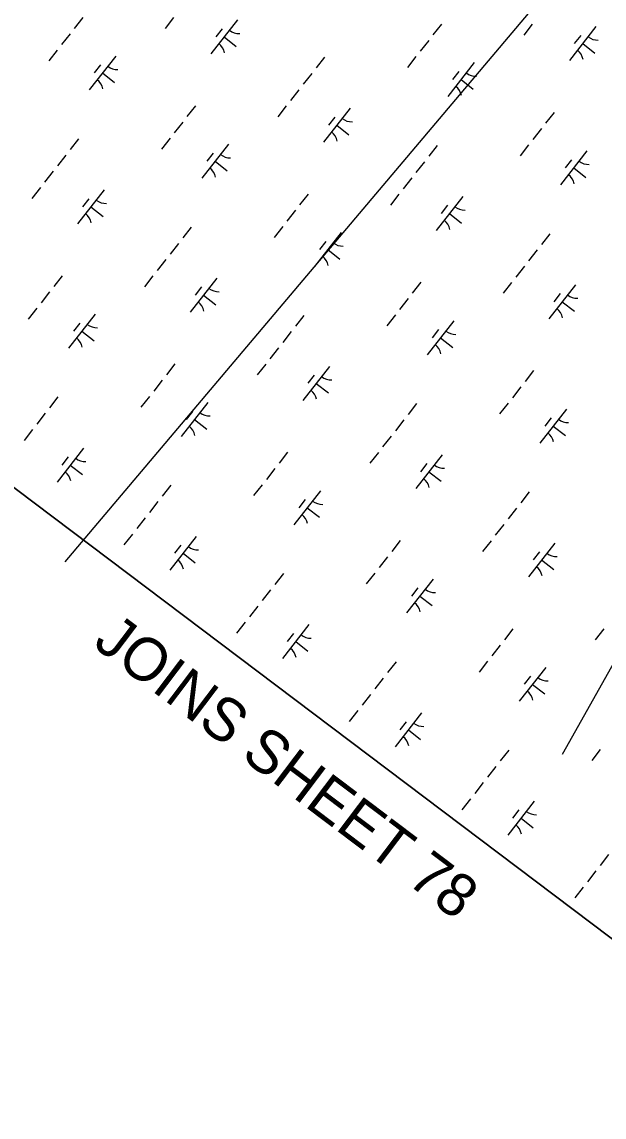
# Model space of a CAD drawing. Extents: x 3896831 to 3918110, y 171006 to 193349.
# Drawn here: x 3902228 to 3902905, y 175445 to 176718 of the extents above; entities that cross this region are included whole.
import ezdxf

# ---------------------------------------------------------------- set-up
doc = ezdxf.new("R2010")
doc.units = 0
for name, color, linetype in [('V-ANNO-TEXT', 7, 'Continuous'), ('V-GRID-FRAM', 7, 'Continuous'), ('V-UTIL-LINE', 7, 'Continuous'), ('V-WETL-SWMP', 7, 'Continuous')]:
    doc.layers.add(name, color=color, linetype=linetype)

msp = doc.modelspace()

# ---------------------------------------------------------------- linework, layer by layer
at = {"layer": 'V-GRID-FRAM'}
msp.add_lwpolyline([(3916044.9, 184610), (3906752.8, 172754.1), (3900055.1, 177809.8), (3909313.3, 189695.8), (3916044.9, 184610)], dxfattribs=at)
at = {"layer": 'V-UTIL-LINE'}
for points in [[(3911670.5, 187980.3), (3909726.1, 186106.6), (3909690.7, 186047.7), (3909490.4, 185423.1), (3908571.2, 184256.5), (3908123.4, 183643.7), (3907157.1, 182394.6), (3906544.4, 181593.3), (3906120.1, 181051.2), (3905460.2, 180002.4), (3904670.7, 178765.1), (3903951.9, 177622.1), (3903445.2, 176832.5), (3902962, 176054.8), (3902856, 175866.2)], [(3902278.5, 176090.1), (3904647.1, 178894.7), (3905719.5, 180143.9), (3906520.8, 181098.4), (3907322.1, 182041.1), (3907534.2, 182300.3), (3908041, 182924.9), (3909514, 184881.1), (3910138.5, 185694.2), (3909821.8, 185935.5), (3909829.3, 185945.1), (3909882.7, 185907)]]:
    msp.add_lwpolyline(points, dxfattribs=at)
at = {"layer": 'V-WETL-SWMP'}
for p, q in [((3901222.6, 176928.5), (3903106.7, 175506.3)), ((3902299, 176722.8), (3902289.1, 176710.2)), ((3902404.4, 176722.7), (3902394.6, 176710.1)), ((3902478.6, 176719.9), (3902447.7, 176680.6)), ((3902715.6, 176715.1), (3902705.7, 176702.5)), ((3902821.1, 176715), (3902811.2, 176702.4)), ((3902895.2, 176712.2), (3902864.4, 176672.9)), ((3902284.2, 176703.9), (3902274.3, 176691.3)), ((3902460.8, 176709.7), (3902453.4, 176700.3)), ((3902463.1, 176700.2), (3902477.3, 176689.1)), ((3902877.4, 176702), (3902870, 176692.6)), ((3902269.3, 176685), (3902259.5, 176672.4)), ((3902700.8, 176696.2), (3902690.9, 176683.6)), ((3902879.8, 176692.5), (3902893.9, 176681.4)), ((3902337.2, 176678), (3902306.3, 176638.6)), ((3902579.8, 176676.7), (3902569.9, 176664.1)), ((3902686, 176677.3), (3902676.1, 176664.7)), ((3902319.4, 176667.8), (3902312, 176658.3)), ((3902753.8, 176670.3), (3902723, 176630.9)), ((3902736, 176660.1), (3902728.6, 176650.6)), ((3902321.7, 176658.3), (3902335.9, 176647.2)), ((3902565, 176657.8), (3902555.1, 176645.2)), ((3902738.4, 176650.6), (3902752.6, 176639.5)), ((3902550.1, 176638.9), (3902540.3, 176626.3)), ((3902429.9, 176620.2), (3902420, 176607.6)), ((3902535.3, 176620.1), (3902525.5, 176607.5)), ((3902609.5, 176617.3), (3902578.6, 176578)), ((3902846.5, 176612.5), (3902836.7, 176599.9)), ((3902415.1, 176601.3), (3902405.2, 176588.7)), ((3902591.7, 176607.1), (3902584.3, 176597.7)), ((3902594.1, 176597.6), (3902608.2, 176586.5)), ((3902831.7, 176593.6), (3902821.8, 176581)), ((3902294, 176581.8), (3902284.2, 176569.2)), ((3902400.3, 176582.4), (3902390.4, 176569.8)), ((3902468.1, 176575.4), (3902437.2, 176536)), ((3902710.7, 176574.1), (3902700.8, 176561.5)), ((3902816.9, 176574.7), (3902807, 176562.1)), ((3902279.2, 176562.9), (3902269.4, 176550.3)), ((3902450.3, 176565.2), (3902442.9, 176555.7)), ((3902884.7, 176567.7), (3902853.9, 176528.3)), ((3902866.9, 176557.5), (3902859.5, 176548)), ((3902452.7, 176555.7), (3902466.8, 176544.6)), ((3902695.9, 176555.2), (3902686, 176542.6)), ((3902869.3, 176548), (3902883.5, 176536.9)), ((3902264.4, 176544), (3902254.6, 176531.4)), ((3902681.1, 176536.3), (3902671.2, 176523.7)), ((3902249.6, 176525.1), (3902239.7, 176512.5)), ((3902323.8, 176522.4), (3902292.9, 176483.1)), ((3902306, 176512.2), (3902298.6, 176502.8)), ((3902560.8, 176517.6), (3902550.9, 176505)), ((3902666.3, 176517.4), (3902656.4, 176504.8)), ((3902740.4, 176514.7), (3902709.5, 176475.4)), ((3902308.3, 176502.7), (3902322.5, 176491.6)), ((3902546, 176498.7), (3902536.1, 176486.1)), ((3902722.6, 176504.5), (3902715.2, 176495.1)), ((3902725, 176495), (3902739.1, 176483.9)), ((3902424.9, 176479.2), (3902415.1, 176466.6)), ((3902531.2, 176479.8), (3902521.3, 176467.2)), ((3902599, 176472.8), (3902568.2, 176433.4)), ((3902841.6, 176471.5), (3902831.7, 176458.9)), ((3902410.1, 176460.3), (3902400.3, 176447.7)), ((3902581.2, 176462.6), (3902573.8, 176453.1)), ((3902583.6, 176453.1), (3902597.7, 176442)), ((3902826.8, 176452.6), (3902816.9, 176440)), ((3902395.3, 176441.4), (3902385.5, 176428.8)), ((3902812, 176433.7), (3902802.1, 176421.1)), ((3902275.1, 176422.7), (3902265.2, 176410.1)), ((3902380.5, 176422.5), (3902370.7, 176409.9)), ((3902454.7, 176419.8), (3902423.8, 176380.4)), ((3902436.9, 176409.6), (3902429.5, 176400.2)), ((3902691.7, 176415), (3902681.8, 176402.4)), ((3902797.2, 176414.8), (3902787.3, 176402.2)), ((3902871.3, 176412.1), (3902840.5, 176372.7)), ((3902260.3, 176403.8), (3902250.4, 176391.2)), ((3902439.2, 176400.1), (3902453.4, 176389)), ((3902676.9, 176396.1), (3902667, 176383.5)), ((3902853.5, 176401.9), (3902846.1, 176392.5)), ((3902855.9, 176392.4), (3902870.1, 176381.3)), ((3902245.5, 176384.9), (3902235.6, 176372.3)), ((3902313.3, 176377.8), (3902282.4, 176338.5)), ((3902295.5, 176367.7), (3902288.1, 176358.2)), ((3902555.9, 176376.6), (3902546, 176364)), ((3902662.1, 176377.2), (3902652.2, 176364.6)), ((3902729.9, 176370.1), (3902699.1, 176330.8)), ((3902297.9, 176358.2), (3902312, 176347.1)), ((3902541.1, 176357.7), (3902531.2, 176345.1)), ((3902712.1, 176360), (3902704.7, 176350.5)), ((3902714.5, 176350.5), (3902728.7, 176339.4)), ((3902526.3, 176338.8), (3902516.4, 176326.2)), ((3902406, 176320.1), (3902396.1, 176307.5)), ((3902511.5, 176319.9), (3902501.6, 176307.3)), ((3902585.6, 176317.2), (3902554.7, 176277.8)), ((3902567.8, 176307), (3902560.4, 176297.6)), ((3902822.6, 176312.4), (3902812.8, 176299.8)), ((3902391.2, 176301.2), (3902381.3, 176288.6)), ((3902570.2, 176297.5), (3902584.3, 176286.4)), ((3902807.8, 176293.5), (3902798, 176280.9)), ((3902270.1, 176281.7), (3902260.3, 176269.1)), ((3902376.4, 176282.3), (3902366.5, 176269.7)), ((3902444.2, 176275.2), (3902413.4, 176235.9)), ((3902426.4, 176265), (3902419, 176255.6)), ((3902686.8, 176274), (3902676.9, 176261.4)), ((3902793, 176274.6), (3902783.2, 176262)), ((3902860.8, 176267.5), (3902830, 176228.2)), ((3902255.3, 176262.8), (3902245.5, 176250.2)), ((3902428.8, 176255.6), (3902442.9, 176244.5)), ((3902672, 176255.1), (3902662.1, 176242.5)), ((3902843, 176257.3), (3902835.6, 176247.9)), ((3902240.5, 176243.9), (3902230.7, 176231.3)), ((3902845.4, 176247.9), (3902859.6, 176236.8)), ((3902657.2, 176236.2), (3902647.3, 176223.6)), ((3902299.9, 176222.3), (3902269, 176182.9)), ((3902536.9, 176217.4), (3902527, 176204.9)), ((3902642.4, 176217.3), (3902632.5, 176204.7)), ((3902716.5, 176214.6), (3902685.7, 176175.2)), ((3902282.1, 176212.1), (3902274.7, 176202.6)), ((3902284.4, 176202.6), (3902298.6, 176191.5)), ((3902698.7, 176204.4), (3902691.3, 176194.9)), ((3902522.1, 176198.6), (3902512.2, 176186)), ((3902701.1, 176194.9), (3902715.3, 176183.8)), ((3902401.1, 176179.1), (3902391.2, 176166.5)), ((3902507.3, 176179.7), (3902497.4, 176167.1)), ((3902575.1, 176172.6), (3902544.3, 176133.3)), ((3902817.7, 176171.4), (3902807.8, 176158.8)), ((3902386.3, 176160.2), (3902376.4, 176147.6)), ((3902557.3, 176162.4), (3902549.9, 176153)), ((3902559.7, 176153), (3902573.9, 176141.9)), ((3902802.9, 176152.5), (3902793, 176139.9)), ((3902371.5, 176141.3), (3902361.6, 176128.7)), ((3902788.1, 176133.6), (3902778.2, 176121)), ((3902356.6, 176122.4), (3902346.8, 176109.8)), ((3902430.8, 176119.7), (3902399.9, 176080.3)), ((3902667.8, 176114.8), (3902658, 176102.2)), ((3902773.3, 176114.7), (3902763.4, 176102.1)), ((3902847.4, 176112), (3902816.6, 176072.6)), ((3902413, 176109.5), (3902405.6, 176100)), ((3902415.4, 176100), (3902429.5, 176088.9)), ((3902829.6, 176101.8), (3902822.2, 176092.3)), ((3902653, 176095.9), (3902643.2, 176083.4)), ((3902832, 176092.3), (3902846.2, 176081.2)), ((3902532, 176076.5), (3902522.1, 176063.9)), ((3902638.2, 176077.1), (3902628.3, 176064.5)), ((3902706, 176070), (3902675.2, 176030.7)), ((3902517.2, 176057.6), (3902507.3, 176045)), ((3902688.2, 176059.8), (3902680.8, 176050.4)), ((3902690.6, 176050.3), (3902704.8, 176039.2)), ((3902502.4, 176038.7), (3902492.5, 176026.1)), ((3902487.6, 176019.8), (3902477.7, 176007.2)), ((3902561.7, 176017.1), (3902530.9, 175977.7)), ((3902798.7, 176012.2), (3902788.9, 175999.6)), ((3902904.2, 176012.1), (3902894.3, 175999.5)), ((3902543.9, 176006.9), (3902536.5, 175997.4)), ((3902546.3, 175997.4), (3902560.4, 175986.3)), ((3902783.9, 175993.3), (3902774.1, 175980.7)), ((3902662.9, 175973.9), (3902653, 175961.3)), ((3902769.1, 175974.5), (3902759.3, 175961.9)), ((3902837, 175967.4), (3902806.1, 175928.1)), ((3902648.1, 175955), (3902638.2, 175942.4)), ((3902819.2, 175957.2), (3902811.8, 175947.8)), ((3902821.5, 175947.7), (3902835.7, 175936.6)), ((3902633.3, 175936.1), (3902623.4, 175923.5)), ((3902618.5, 175917.2), (3902608.6, 175904.6)), ((3902692.6, 175914.5), (3902661.8, 175875.1)), ((3902674.8, 175904.3), (3902667.4, 175894.8)), ((3902677.2, 175894.8), (3902691.4, 175883.7)), ((3902793.8, 175871.3), (3902783.9, 175858.7)), ((3902900.1, 175871.8), (3902890.2, 175859.2)), ((3902779, 175852.4), (3902769.1, 175839.8)), ((3902764.2, 175833.5), (3902754.3, 175820.9)), ((3902749.4, 175814.6), (3902739.5, 175802)), ((3902823.5, 175811.8), (3902792.7, 175772.5)), ((3902805.7, 175801.7), (3902798.3, 175792.2)), ((3902808.1, 175792.2), (3902822.3, 175781.1)), ((3902909.9, 175749.8), (3902900.1, 175737.2)), ((3902895.1, 175730.9), (3902885.3, 175718.3)), ((3902880.3, 175712), (3902870.5, 175699.4))]:
    msp.add_line(p, q, dxfattribs=at)
for centre, start, end in [((3902480.4, 176721.8), 231.1403, 272.6839), ((3902897, 176714.1), 231.1403, 272.6839), ((3902446.3, 176678.4), 11.1403, 52.6839), ((3902862.9, 176670.7), 11.1403, 52.6839), ((3902339, 176679.9), 231.1403, 272.6839), ((3902304.9, 176636.4), 11.1403, 52.6839), ((3902755.6, 176672.2), 231.1403, 272.6839), ((3902721.5, 176628.7), 11.1403, 52.6839), ((3902611.3, 176619.2), 231.1403, 272.6839), ((3902577.2, 176575.8), 11.1403, 52.6839), ((3902469.9, 176577.3), 231.1403, 272.6839), ((3902435.8, 176533.8), 11.1403, 52.6839), ((3902886.5, 176569.6), 231.1403, 272.6839), ((3902852.5, 176526.1), 11.1403, 52.6839), ((3902325.6, 176524.3), 231.1403, 272.6839), ((3902291.5, 176480.8), 11.1403, 52.6839), ((3902742.2, 176516.6), 231.1403, 272.6839), ((3902708.1, 176473.1), 11.1403, 52.6839), ((3902600.8, 176474.7), 231.1403, 272.6839), ((3902566.7, 176431.2), 11.1403, 52.6839), ((3902456.5, 176421.7), 231.1403, 272.6839), ((3902422.4, 176378.2), 11.1403, 52.6839), ((3902873.1, 176414), 231.1403, 272.6839), ((3902839, 176370.5), 11.1403, 52.6839), ((3902315.1, 176379.8), 231.1403, 272.6839), ((3902731.7, 176372.1), 231.1403, 272.6839), ((3902281, 176336.3), 11.1403, 52.6839), ((3902697.6, 176328.6), 11.1403, 52.6839), ((3902587.4, 176319.1), 231.1403, 272.6839), ((3902553.3, 176275.6), 11.1403, 52.6839), ((3902446, 176277.2), 231.1403, 272.6839), ((3902862.6, 176269.5), 231.1403, 272.6839), ((3902411.9, 176233.7), 11.1403, 52.6839), ((3902828.6, 176226), 11.1403, 52.6839), ((3902301.7, 176224.2), 231.1403, 272.6839), ((3902718.3, 176216.5), 231.1403, 272.6839), ((3902267.6, 176180.7), 11.1403, 52.6839), ((3902684.2, 176173), 11.1403, 52.6839), ((3902576.9, 176174.5), 231.1403, 272.6839), ((3902542.8, 176131.1), 11.1403, 52.6839), ((3902432.6, 176121.6), 231.1403, 272.6839), ((3902849.2, 176113.9), 231.1403, 272.6839), ((3902398.5, 176078.1), 11.1403, 52.6839), ((3902815.2, 176070.4), 11.1403, 52.6839), ((3902707.8, 176071.9), 231.1403, 272.6839), ((3902673.8, 176028.5), 11.1403, 52.6839), ((3902563.5, 176019), 231.1403, 272.6839), ((3902529.4, 175975.5), 11.1403, 52.6839), ((3902838.8, 175969.3), 231.1403, 272.6839), ((3902804.7, 175925.9), 11.1403, 52.6839), ((3902694.4, 175916.4), 231.1403, 272.6839), ((3902660.3, 175872.9), 11.1403, 52.6839), ((3902825.3, 175813.8), 231.1403, 272.6839), ((3902791.3, 175770.3), 11.1403, 52.6839)]:
    msp.add_arc(centre, 17.6, start, end, dxfattribs=at)

# ---------------------------------------------------------------- texts
at = {"layer": 'V-ANNO-TEXT'}
msp.add_text('JOINS SHEET 78', height=50, rotation=322.9121, dxfattribs=at).set_placement((3902309.3, 175992.8))

doc.saveas('drawing.dxf')
